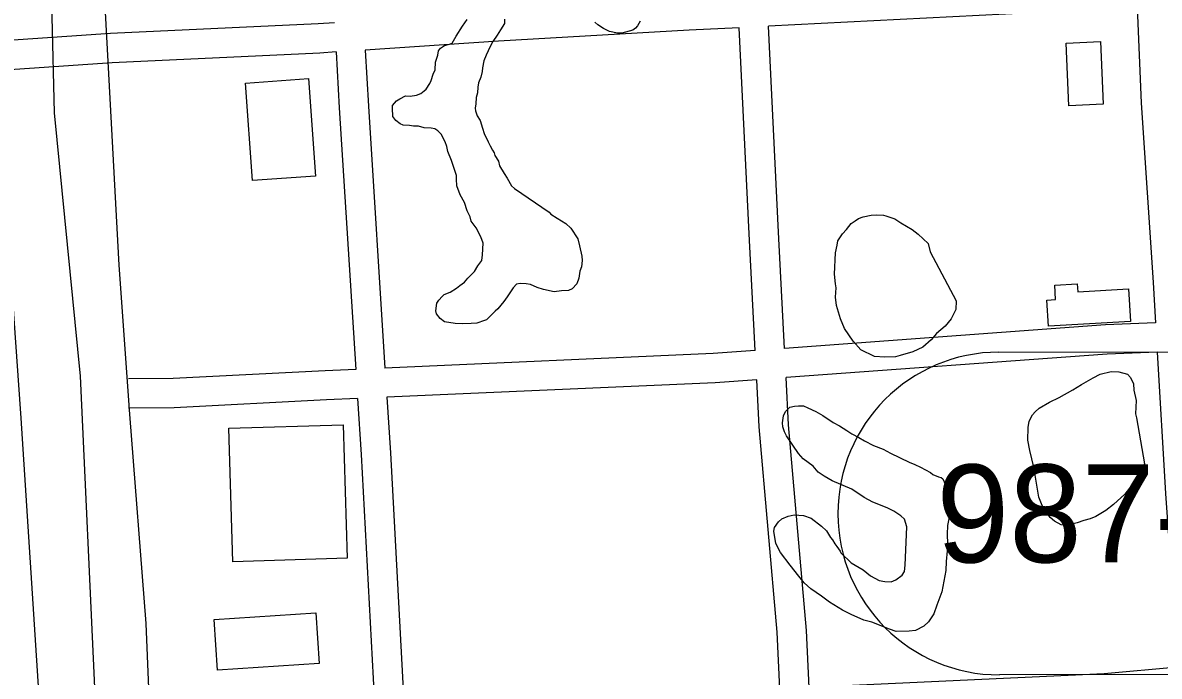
# Model space of a CAD drawing. Extents: x 3313447 to 3351316, y 703786 to 729172.
# Drawn here: x 3319454 to 3320617, y 711460 to 712128 of the extents above; entities that cross this region are included whole.
import ezdxf

# ---------------------------------------------------------------- set-up
doc = ezdxf.new("R2010")
doc.units = 0
for name, color, linetype in [('V-BLDG-OTLN', 7, 'Continuous'), ('V-ROAD-CNTR', 7, 'Continuous'), ('V-ROAD-IDEN', 7, 'Continuous'), ('V-SITE-VEGE', 7, 'Continuous')]:
    doc.layers.add(name, color=color, linetype=linetype)

msp = doc.modelspace()

# ---------------------------------------------------------------- linework, layer by layer
at = {"layer": 'V-BLDG-OTLN'}
for points in [[(3320556.6, 712109.1), (3320559.5, 712045), (3320524.5, 712043.4), (3320521.6, 712107.5)], [(3319746.7, 712071.2), (3319753.7, 711971.5), (3319689.1, 711966.9), (3319682, 712066.6)], [(3320587.4, 711822.8), (3320503.5, 711817.9), (3320502, 711844.8), (3320510.8, 711845.3), (3320509.9, 711859.9), (3320533, 711861.2), (3320533.5, 711853.3), (3320585.5, 711856.3)], [(3319786.2, 711580.8), (3319669.2, 711577.2), (3319665, 711713.6), (3319782, 711717.2)], [(3319757.4, 711473), (3319653.3, 711466.2), (3319649.9, 711518), (3319754, 711524.8)]]:
    msp.add_lwpolyline(points, close=True, dxfattribs=at)
at = {"layer": 'V-ROAD-CNTR'}
for points in [[(3319200.9, 715645.2), (3319216.7, 715284.7), (3319244.5, 714946.5), (3319270.4, 714529.8), (3319298.1, 714304.8), (3319315.2, 714045.1), (3319323.1, 713889.3), (3319368.3, 713112.6), (3319381.2, 712941.1), (3319413.2, 712432.8), (3319431.1, 712024.6), (3319452.3, 711724), (3319471.1, 711433.8), (3319475.9, 711305), (3319509.5, 710784.1), (3319530, 710456), (3319546.3, 710208.9), (3319558.3, 710026.2), (3319565.2, 709880.1), (3319575.7, 709725.1), (3319582.8, 709519.2), (3319592.9, 709284.4), (3319593.2, 709171.8)], [(3319345.1, 714514.6), (3319371.4, 714068), (3319378, 713881.8), (3319405.6, 713508.6), (3319432.4, 713115.5), (3319435.8, 712944.4), (3319467.3, 712512), (3319484.1, 712134.4), (3319486.5, 712036.3), (3319512.8, 711766.8), (3319527.8, 711448.5), (3319527.4, 711327.4), (3319550.9, 711036.9), (3319567.8, 710785.7), (3319575.8, 710627.4), (3319594.4, 710397.1), (3319599, 710295), (3319616.4, 710052.6), (3319624.9, 709858.9), (3319631.7, 709695.3), (3319643.5, 709583.2), (3319653.2, 709388.3), (3319647.9, 709299.2), (3319653.3, 709171.9)], [(3319587.1, 711356.9), (3319580.5, 711514.1), (3319563.9, 711728.2), (3319553, 711880.5), (3319533.8, 712234.2), (3319521.4, 712445.2), (3319511, 712570.7), (3319496.5, 712813.3), (3319483, 713033.5), (3319475.3, 713161.6), (3319462.6, 713404.7), (3319451.4, 713625.4)], [(3320594.3, 712143.9), (3320217.1, 712124.7)], [(3320594.3, 712143.9), (3320598.3, 712046.3), (3320610.7, 711862.6), (3320613, 711821.6)], [(3319773, 712128.3), (3319756.4, 712127.2), (3319543.9, 712117.2), (3319340, 712103.2), (3319236.9, 712101), (3318982.1, 712075.2)], [(3320187.1, 712123.2), (3320136.1, 712120.6), (3319941, 712109.6), (3319804.6, 712100.4)], [(3320203.6, 711793.1), (3320197.5, 711912.6), (3320187.1, 712123.2)], [(3320233.5, 711795.3), (3320227.4, 711914.1), (3320217.1, 712124.7)], [(3319774.7, 712098.4), (3319758.2, 712097.2), (3319545.6, 712087.2), (3319341.4, 712073.3), (3319238.7, 712071), (3318984.1, 712045.2)], [(3319774.7, 712098.4), (3319778, 712041.2), (3319794.9, 711773.9)], [(3319804.6, 712100.4), (3319807.9, 712043), (3319824.8, 711775.2)], [(3320613, 711821.6), (3320561.9, 711819.3), (3320233.5, 711795.3)], [(3320203.6, 711793.1), (3320160.6, 711790), (3319824.8, 711775.2)], [(3320614.8, 711791.6), (3320563.6, 711789.4), (3320235.1, 711765.4)], [(3320614.8, 711791.6), (3320623.2, 711647), (3320636, 711469.2)], [(3319794.9, 711773.9), (3319763.5, 711772.5), (3319608.2, 711764.5), (3319562.3, 711764.2)], [(3320205.1, 711763.2), (3320162.4, 711760), (3319826.7, 711745.3)], [(3320228.8, 711447.2), (3320226.1, 711505), (3320207.6, 711715.1), (3320205.1, 711763.2)], [(3320258.8, 711448.6), (3320256.1, 711507), (3320237.5, 711717.2), (3320235.1, 711765.4)], [(3319826.7, 711745.3), (3319830.3, 711688.5), (3319844.8, 711421.1)], [(3319796.8, 711744), (3319764.9, 711742.6), (3319609.1, 711734.5), (3319562.5, 711734.2)], [(3319796.8, 711744), (3319800.4, 711686.8), (3319814.9, 711419.7)], [(3320636, 711469.2), (3320560.4, 711462.7), (3320258.8, 711448.6)]]:
    msp.add_lwpolyline(points, dxfattribs=at)
at = {"layer": 'V-ROAD-IDEN'}
for p, q in [((3320452.8, 711791.5), (3320782.8, 711792)), ((3320452.8, 711791.5), (3320782.8, 711792)), ((3320452.8, 711791.5), (3320452.8, 711791.5)), ((3320783.3, 711462), (3320453.3, 711461.5)), ((3320783.3, 711462), (3320453.3, 711461.5))]:
    msp.add_line(p, q, dxfattribs=at)
msp.add_arc((3320453.1, 711626.5), 165, 90.0834, 270.0834, dxfattribs=at)
msp.add_arc((3320453.1, 711626.5), 165, 90.0834, 270.0834, dxfattribs=at)
at = {"layer": 'V-SITE-VEGE'}
for points in [[(3319904, 712124.7), (3319908.8, 712131.6)], [(3319947.2, 712132.1), (3319947, 712127.5), (3319942.8, 712121.2), (3319939.4, 712115.5), (3319935.2, 712109.2), (3319932.4, 712104.1), (3319928.2, 712095.1), (3319926, 712089.4), (3319924.4, 712082.3), (3319924.3, 712078.4), (3319922.7, 712072.6), (3319920.6, 712066.8), (3319919.7, 712062.3), (3319919.5, 712056.5), (3319918, 712052), (3319917.8, 712045.5), (3319916.9, 712040.9), (3319917.5, 712038.3), (3319919.2, 712033.1), (3319922.3, 712028.4), (3319924.6, 712020.5), (3319926.3, 712015.2), (3319930.5, 712006.6), (3319932.3, 712002.6), (3319934.8, 711998), (3319936.6, 711995.3), (3319937.1, 711992.7), (3319940.8, 711986.7), (3319941.9, 711982.1), (3319946.8, 711974.1), (3319949.9, 711969.4), (3319954.1, 711961.5), (3319957.3, 711958.7), (3319992.7, 711934.6)], [(3320085.7, 712129.9), (3320083.2, 712125.1), (3320081.1, 712122.8), (3320078.4, 712120.6), (3320067, 712117.8), (3320062.7, 712117.6), (3320054.5, 712119.3), (3320048.4, 712122.5), (3320042.5, 712126.3), (3320039.3, 712128.8)], [(3319992.7, 711934.6), (3319994.6, 711932.6), (3320000.9, 711928.4), (3320009.8, 711922.9), (3320014.8, 711918.1), (3320022.2, 711907.4), (3320023.9, 711900.2), (3320026.1, 711889.7), (3320026.6, 711885.1), (3320025.7, 711878.7), (3320024.2, 711874.2), (3320023.2, 711867.1), (3320021.1, 711861.3), (3320016.3, 711856.3), (3320012.4, 711854.5), (3320005.2, 711854.1), (3319998, 711853.1), (3319987, 711855.5), (3319980.6, 711857.7), (3319973.6, 711860.6), (3319969.1, 711861.4), (3319963.2, 711861.6), (3319959.3, 711861.1), (3319955.9, 711857.4), (3319949.7, 711847.9), (3319946.2, 711843.4), (3319940.1, 711835.9), (3319937.4, 711833.4), (3319928.6, 711824.6), (3319926.6, 711824), (3319918.7, 711821.1), (3319912.8, 711820.7), (3319903.7, 711820.4), (3319896.6, 711820.7), (3319885.6, 711822.4), (3319881.2, 711825.8), (3319877.5, 711830.5), (3319876.9, 711833.8), (3319877.9, 711841.6), (3319880, 711844.7), (3319883.4, 711848.5), (3319885.4, 711850.4), (3319891.3, 711852.7), (3319898, 711857), (3319901.4, 711859.5), (3319906.1, 711863.2), (3319909.5, 711867), (3319916.2, 711873.9), (3319919.7, 711879.6), (3319923.8, 711885.3), (3319924.7, 711891.1), (3319925.2, 711902.8), (3319922.8, 711909.4), (3319918, 711918.7), (3319913.1, 711925.4), (3319911.9, 711930), (3319908.9, 711935.9), (3319906, 711944.5), (3319901.8, 711952.5), (3319898.2, 711961.7), (3319897.8, 711968.2), (3319898, 711972.1), (3319892.7, 711987.3), (3319889.2, 711996.5), (3319888.1, 712001.8), (3319886.3, 712006.4), (3319882.1, 712014.4), (3319879, 712017.7), (3319875.8, 712019.8), (3319871.9, 712020.6), (3319864.8, 712020.9), (3319859, 712022.4), (3319853.8, 712022.6), (3319849.9, 712023.4), (3319843.4, 712023.7), (3319840.2, 712025.1), (3319835.8, 712028.5), (3319832.7, 712032.5), (3319832.4, 712041), (3319832.5, 712043.6), (3319836.6, 712048.6), (3319839.9, 712050.5), (3319845.9, 712053.5), (3319850.4, 712053.3), (3319857, 712054.4), (3319861.6, 712056.1), (3319865, 712058.6), (3319867, 712060.5), (3319870.5, 712066.2), (3319871.9, 712069.4), (3319874.1, 712075.8), (3319876.2, 712080.3), (3319876.5, 712088), (3319878.7, 712095.1), (3319879.6, 712099.6), (3319881.6, 712102.2), (3319885.6, 712105.2), (3319890.9, 712106.3), (3319893.5, 712107.5), (3319897.7, 712114.5), (3319904, 712124.7)]]:
    msp.add_lwpolyline(points, dxfattribs=at)
for points in [[(3320409.2, 711844.1), (3320408.9, 711835), (3320403.9, 711825.5), (3320397.8, 711817.9), (3320389.1, 711810.5), (3320383.6, 711804.2), (3320374.9, 711796.7), (3320364.9, 711791.9), (3320351.8, 711787.9), (3320347.2, 711786.7), (3320336.1, 711786.5), (3320325.7, 711786.9), (3320311.7, 711794), (3320303.6, 711802.8), (3320295, 711815.5), (3320290.8, 711825.4), (3320286.8, 711839.2), (3320285.8, 711847.7), (3320286.2, 711857.4), (3320285.7, 711861.3), (3320284.8, 711871.1), (3320285.7, 711893.2), (3320287.3, 711900.9), (3320288.1, 711905.4), (3320292.9, 711912.4), (3320297, 711916.8), (3320301.8, 711923.1), (3320305.8, 711925.6), (3320309.1, 711928), (3320313.8, 711929.8), (3320322.3, 711931.4), (3320328.1, 711931.8), (3320334.6, 711931.6), (3320337.2, 711930.8), (3320346.2, 711927.9), (3320352.5, 711923.7), (3320364, 711916.8), (3320370.3, 711912), (3320380.3, 711902.5), (3320382.6, 711893.9)], [(3320601.6, 711677.3), (3320598.1, 711670.9), (3320594, 711663.9), (3320586.4, 711652.5), (3320581.6, 711646.2), (3320570.1, 711635.6), (3320562.1, 711629.4), (3320552.1, 711623.3), (3320546.1, 711620.9), (3320539.6, 711619.2), (3320533, 711616.9), (3320523.1, 711614.7), (3320516.6, 711614.9), (3320509.6, 711618.5), (3320505.2, 711622.5), (3320497.2, 711634.6), (3320493.7, 711643.2), (3320491.1, 711659.5), (3320488.4, 711673.9), (3320484.5, 711691), (3320482.3, 711701.5), (3320482.8, 711714.5), (3320483.7, 711720.9), (3320487.2, 711727.3), (3320489.9, 711730.4), (3320494, 711734.2), (3320504.6, 711740.3), (3320514.6, 711745.1), (3320528.5, 711753), (3320537.2, 711758.5), (3320549.2, 711765.2), (3320556.5, 711768.8), (3320567.6, 711771.6), (3320575.4, 711771.3), (3320584.4, 711769), (3320587.6, 711765.6), (3320590.5, 711759), (3320590.9, 711752.5), (3320593.1, 711742), (3320592.6, 711728.3), (3320593.7, 711724.4)], [(3320405.7, 711638.8), (3320402.6, 711626.6), (3320400.2, 711614.3), (3320399.9, 711605.2), (3320400.1, 711595.5), (3320399.8, 711588.3), (3320398.8, 711577.3), (3320398.4, 711568.2), (3320394.3, 711546.3), (3320389.2, 711532.8), (3320386.3, 711523.8), (3320380.7, 711515.6), (3320376, 711511.2), (3320367.4, 711507), (3320360.9, 711506), (3320347.8, 711505.8), (3320340.8, 711508.1), (3320322.9, 711515.3), (3320314.5, 711517.5), (3320301.7, 711523.2), (3320292.8, 711527.5), (3320279.4, 711535.8), (3320271.2, 711542), (3320260.5, 711549.6), (3320253.6, 711555.7), (3320248, 711562.4), (3320239.3, 711573.8), (3320229.4, 711586.5), (3320224.6, 711595.8), (3320222.5, 711608.3), (3320223.3, 711612.1), (3320227.4, 711617.8), (3320230.8, 711621), (3320237.4, 711623.9), (3320243.3, 711625), (3320253, 711624.6), (3320260.7, 711621.7), (3320271.4, 711613.5), (3320276.5, 711608.8), (3320280.7, 711602.1), (3320282.6, 711599.4), (3320285, 711595.4), (3320286.9, 711592.7), (3320290.6, 711588), (3320291.2, 711586.1), (3320301.8, 711575.9), (3320313.9, 711568.9), (3320321.5, 711562.8), (3320330.4, 711557.9), (3320336.2, 711557), (3320342.7, 711556.7), (3320347.3, 711558.5), (3320354, 711563.5), (3320356.1, 711567.3), (3320357, 711573.7), (3320358.5, 711612.7), (3320356.2, 711620.6), (3320352.5, 711624), (3320345.5, 711628.8), (3320338.5, 711632.3), (3320323.8, 711638.1), (3320314.9, 711643), (3320302.2, 711651.3), (3320282.4, 711659.9), (3320274.1, 711664.8), (3320267.8, 711668.9), (3320262.8, 711675), (3320252.7, 711682.5), (3320247.7, 711687.9), (3320235.4, 711705.9), (3320233.6, 711709.9), (3320231.9, 711715.2), (3320231.4, 711719.1), (3320232.3, 711726.2), (3320234.4, 711730.7), (3320239.1, 711735.1), (3320243.7, 711736.2), (3320247.7, 711736.7), (3320252.9, 711736.5), (3320257.3, 711734.4), (3320265.6, 711730.8), (3320272.6, 711726.6), (3320283.4, 711719.7), (3320289.8, 711716.2), (3320297.4, 711711.3), (3320302.5, 711707.9), (3320309.5, 711704.3), (3320315.2, 711700.9), (3320324.7, 711695.9), (3320334.3, 711692.3), (3320342, 711688.1), (3320361.1, 711678.9), (3320366.9, 711676.7), (3320372.6, 711673.9), (3320382.8, 711668.3), (3320385.3, 711666.3), (3320391.1, 711664.1), (3320393.7, 711663.3), (3320395.6, 711662)]]:
    msp.add_lwpolyline(points, close=True, dxfattribs=at)

# ---------------------------------------------------------------- texts
at = {"layer": 'V-ROAD-IDEN'}
msp.add_text('987-6', height=100, rotation=0.0835, dxfattribs=at).set_placement((3320389, 711576.4))

doc.saveas('drawing.dxf')
